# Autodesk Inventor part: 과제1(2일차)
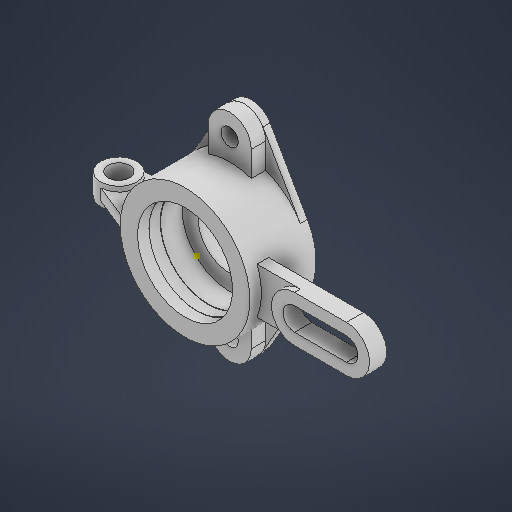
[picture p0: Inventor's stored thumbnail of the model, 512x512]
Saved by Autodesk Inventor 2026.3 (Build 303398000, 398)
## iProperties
Created: 2026-08
Part Number: 과제1(2일차)
Material: 일반
Document SubType Name: Modeling
Designer: chang
Density: 1 g/cm^3
Appearance: 기본값
Author: chang
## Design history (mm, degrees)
sketch "스케치1"
  geometry: L1 (-12.874, 67.522)-(-38.932, 22.567); L2 (13.107, 67.477)-(39.01, 22.433); L3 (-39.01, -22.433)-(-13.107, -67.477); L4 (12.874, -67.522)-(38.932, -22.567); C1 r 22 at (0, 0); C2 r 6 at (0.104, 60); C3 r 6 at (-0.104, -60); A1 r 15 centre (0.104, 60) between (13.107, 67.477) and (-12.874, 67.522); A2 r 15 centre (-0.104, -60) between (-13.107, -67.477) and (12.874, -67.522); A3 r 45 centre (0, 0) between (-38.932, 22.567) and (-39.01, -22.433); A4 r 45 centre (0, 0) between (38.932, -22.567) and (39.01, 22.433); 1 further point
  constraints: 11 tangent, 8 end point, 8 point on circle, 7 centre point, 4 coincident, 2 parallel
  dimensions: "d7" = 44 diameter of C1; "d8" = 12 diameter of C2; "d9" = 12 diameter of C3; "d12" = 15.00001 radius of A1; "d13" = 45 radius of A4; "d14" = 77.94218 distance of L2.end L1.end
extrude "돌출1" new body sketch "스케치1" distance "d15" = 5; taper "d16" = 0 deg
sketch "스케치2"
  geometry: L1 (-15, -60)-(-15, -42.426); L2 (15, -60)-(15, -42.426); L3 (-15, 60)-(-15, 42.426); L4 (15, 60)-(15, 42.426); C1 r 6 at (0, 60); C2 r 6 at (0, -60); A1 r 45 centre (0, 0) between (-15, -42.426) and (15, -42.426); A2 r 15 centre (0, 60) between (15, 60) and (-15, 60); A3 r 15 centre (0, -60) between (-15, -60) and (15, -60); 1 further point
  constraints: 8 end point, 8 point on circle, 5 centre point, 4 point on line, 3 coincident, 1 parallel, 1 vertical
sketch "스케치3"
  geometry: 1 further point
extrude "돌출2" join sketch "스케치2" distance "d22" = 10; taper "d23" = 0 deg
sketch "스케치4"
  geometry: C1 r 22 at (0, 0); 1 further point
  constraints: 1 centre point, 1 coincident
  dimensions: "d24" = 44 diameter of C1
extrude "돌출3" cut sketch "스케치4" distance "d25" = 10; taper "d26" = 0 deg
sketch "스케치7"
  geometry: 1 further point
sketch "스케치9"
  geometry: C1 r 33 at (0, 0); C2 r 45 at (0, 0); 1 further point
  constraints: 2 centre point, 2 coincident
  dimensions: "d31" = 66 diameter of C1; "d32" = 90 diameter of C2
extrude "돌출5" join sketch "스케치9" distance "d33" = 15; taper "d34" = 0 deg
sketch "스케치10"
  geometry: L1 (42.059, 16)-(72.059, 16); L2 (42.059, -16)-(72.059, -16); L3 (72.059, 16)-(108.059, 16); L4 (72.059, -16)-(108.059, -16); L5 (72.059, 8)-(108.059, 8); L6 (72.059, -8)-(108.059, -8); C1 r 33.307 at (0, 0); A1 r 45 centre (0, 0) between (42.059, -16) and (42.059, 16); A2 r 16 centre (72.059, 0) between (72.059, 16) and (72.059, -16); A3 r 16 centre (108.059, 0) between (108.059, -16) and (108.059, 16); A4 r 8 centre (72.059, 0) between (72.059, 8) and (72.059, -8); A5 r 8 centre (108.059, 0) between (108.059, -8) and (108.059, 8); 1 further point
  constraints: 12 end point, 10 point on circle, 6 centre point, 4 coincident, 4 tangent
  dimensions: "d37" = 30 distance of L1.start L1.end
extrude "돌출6" join sketch "스케치10" distance "d43" = 8; taper "d44" = 0 deg
sketch "스케치11"
  geometry: 1 further point
sketch "스케치12"
  geometry: L1 (72.059, 16)-(108.059, 16); L2 (72.059, -16)-(108.059, -16); L3 (72.059, 8)-(108.059, 8); L4 (72.059, -8)-(108.059, -8); L5 (72.059, 8)-(108.059, 8); A1 r 8 centre (72.059, 0) between (72.059, 8) and (72.059, -8) reference; A2 r 16 centre (72.059, 0) between (72.059, 16) and (72.059, -16); A3 r 8 centre (108.059, 0) between (108.059, -8) and (108.059, 8); A4 r 16 centre (108.059, 0) between (108.059, -16) and (108.059, 16); 1 further point
  constraints: 10 end point, 6 point on circle, 4 tangent, 3 centre point, 1 coincident
extrude "돌출7" join sketch "스케치12" distance "d49" = 4; taper "d50" = 0 deg
sketch "스케치13"
  geometry: C1 r 33 at (0, 0); C2 r 45 at (0, 0); 1 further point
  constraints: 2 centre point, 2 coincident
  dimensions: "d51" = 66 diameter of C1; "d52" = 90 diameter of C2
extrude "돌출8" join sketch "스케치13" distance "d53" = 8; taper "d54" = 0 deg
node "작업 평면2"
sketch "스케치14"
  geometry: L1 (6.029, 0)-(0, 0) reference; L2 (-25, 9.5)-(0, 9.5) reference; L3 (0, 0)-(0, 46) reference; L4 (0, 44.5)-(-25, 34.5) reference; L5 (0, 44.5)-(1, 44.5); L6 (0, 44.5)-(1, 44.5); L7 (1, 44.5)-(1, 9.5); L8 (1, 9.5)-(0, 9.5); A1 r 12.5 centre (-25, 22) between (-25, 9.5) and (-25, 34.5) reference; 1 further point
  constraints: 12 end point, 3 horizontal, 2 point on circle, 1 centre point, 1 collinear, 1 perpendicular, 1 point on line, 2 other
  dimensions: "d65" = 1 distance of L4.start L5.end; "d66" = 0 distance between parallel lines of L5 L6 (derived); "d67" = 35 distance of L5.end L7.end; "d68" = 90 deg angle of L5 L7
extrude "돌출9" join sketch "스케치14" stored distance "d59" = 8; taper "d60" = 0 deg
sketch "스케치15"
  geometry: L1 (-25, 34.5)-(0, 44.5) reference; L2 (-25, 9.5)-(0.178, 9.5) reference; C1 r 12.5 at (-25, 22); C2 r 7.5 at (-25, 22); 2 further points
  constraints: 2 centre point, 1 coincident
  dimensions: "d62" = 15 diameter of C2
extrude "돌출10" join sketch "스케치15" stored distance "d63" = 15; taper "d64" = 0 deg
node "솔리드1"
